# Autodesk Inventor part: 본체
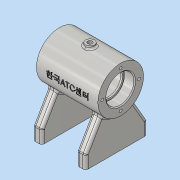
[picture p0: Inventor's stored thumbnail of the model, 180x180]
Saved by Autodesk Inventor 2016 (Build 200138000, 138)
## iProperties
Created: 2018-05
Part Number: 본체
Material: 알루미늄 6061
Document SubType Name: Modeling
Designer: Administrator
Density: 2.7 g/cm^3
Appearance: 알루미늄 - 평지
Mass: 317.681 g
Surface Area: 375.828 cm^2
Volume: 117.66 cm^3
Author: Administrator
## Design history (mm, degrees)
sketch "스케치1"
  geometry: L1 (-25, 0)-(0, 0); L2 (-20, 35)-(-30, 35); L3 (-30, 35)-(-30, -35); L4 (-30, -35)-(-20, -35); L5 (-20, -35)-(-20, 35); L6 (-20, 35)-(-30, -35); L7 (-30, 35)-(-20, -35)
  constraints: 14 end point, 2 horizontal, 2 midpoint, 2 parallel, 1 perpendicular
  dimensions: "d0" = 25 distance of L1.start L1.end; "d1" = 10 distance of L4.end L3.end; "d2" = 70 distance of L3.end L2.end
extrude "돌출1" new body sketch "스케치1" distance "d3" = 15; taper "d4" = 0 deg
sketch "스케치2"
  geometry: L1 (35, 65)-(-35, 65); L2 (35, 65)-(35, 91); L3 (35, 91)-(-35, 91); L4 (-35, 91)-(-35, 65); 2 further points
  constraints: 8 end point, 2 perpendicular, 1 horizontal, 1 midpoint, 1 vertical, 1 vertical alignment
  dimensions: "d5" = 65 distance from line of point (0, 0) L1; "d6" = 70 distance of L1.start L1.end; "d7" = 52 diameter of L3 L1
revolve "회전1" sketch "스케치2" stored, may be unused: angle "d8" = 90 deg
node "작업 평면1"
sketch "스케치3"
  geometry: L1 (-35, 15)-(35, 15) reference; L2 (-35, 15)-(-16.972, 46.226); L3 (-35, 0)-(-35, 15) reference; L4 (0, 0)-(0, 66.177); L5 (35, 15)-(16.972, 46.226); L6 (-35, 15)-(35, 15); L7 (-16.972, 46.226)-(16.972, 46.226)
  constraints: 10 end point, 1 collinear, 1 perpendicular, 1 symmetric about line, 1 vertical
  dimensions: "d10" = 30 deg angle of L3 L2
extrude "돌출2" join sketch "스케치3" stored distance "d11" = 10; taper "d12" = 0 deg
sketch "스케치4"
  geometry: L1 (35, 39)-(35, 91) reference; L2 (35, 65)-(-35, 65); L3 (-35, 39)-(-35, 91) reference; L4 (-35, 39)-(35, 39) reference; L5 (0, 39)-(0, 91); L6 (35, 65)-(35, 81); L7 (35, 81)-(23, 81); L8 (23, 81)-(23, 79); L9 (23, 79)-(21, 79); L10 (21, 79)-(21, 86); L11 (21, 86)-(0, 86); L12 (-23, 79)-(-21, 79); L13 (-35, 65)-(-35, 81); L14 (-35, 81)-(-23, 81); L15 (-23, 81)-(-23, 79); L16 (-21, 79)-(-21, 86); L17 (-21, 86)-(0, 86); 1 further point
  constraints: 28 end point, 5 symmetric about line, 4 perpendicular, 3 midpoint, 2 point on line, 1 horizontal, 1 vertical
  dimensions: "d13" = 32 diameter of L7 L2; "d14" = 28 diameter of L9 L2; "d15" = 42 diameter of L11 L2; "d16" = 12 distance of L6.end L7.end; "d17" = 21 distance of L10.end L11.end
revolve "회전2" sketch "스케치4" stored, may be unused: angle "d18" = 90 deg
node "작업 평면2"
sketch "스케치5"
  geometry: C1 r 5 at (0, 0); 1 further point
  constraints: 1 centre point, 1 coincident
  dimensions: "d20" = 10 diameter of C1
extrude "돌출3" join sketch "스케치5" stored distance "d21" = 10; taper "d22" = 0 deg
sketch "스케치7"
  geometry: 2 further points
  dimensions: "d34" = 20 vertical distance of point (30, -35) point (5, -55)
hole "구멍2" sketch "스케치7" at (5, -55) diameter "d35" = 4.134; stored, may be unused: countersink angle "d39" = 90 deg, drill point angle "d41" = 118 deg; dims "d36" = 8, "d37" = 4, "d38" = 2, "d40" = 10
sketch "스케치8"
  geometry: L1 (0, 65)-(8.893, 40.568); L2 (0, 65)-(0, 57.633); 2 further points
  constraints: 4 end point, 1 coincident, 1 vertical, 2 other
  dimensions: "d48" = 20 deg angle of L1 L2
node "작업 평면4"
  node "작업 평면3"
sketch "스케치9"
  geometry: C1 r 6 at (0, 0); 1 further point
  constraints: 1 centre point
  dimensions: "d50" = 12 diameter of C1
extrude "돌출4" join sketch "스케치9" stored distance "d51" = 10; taper "d52" = 0 deg
hole "구멍3" diameter "d55" = 5.188; stored, may be unused: countersink angle "d59" = 90 deg, drill point angle "d61" = 118 deg; dims "d53" = 10, "d54" = 10, "d56" = 12, "d57" = 4, "d58" = 2, "d60" = 16
hole "구멍4" diameter "d64" = 5.188; stored, may be unused: countersink angle "d68" = 90 deg, drill point angle "d70" = 118 deg; dims "d62" = 10, "d63" = 10, "d65" = 12, "d66" = 4, "d67" = 2, "d69" = 16
node "작업 평면5"
sketch "스케치10"
  geometry: 2 further points
  constraints: 1 other
feature "엠보싱1" sketch "스케치10" dims "d71" = 0.5, "d72" = 0
fillet "모깎기1" dims "d73" = 2, "d74" = 3
chamfer "모따기1" distance "d75" = 1; stored, may be unused: second distance "d76" = 2, angle "d77" = 45 deg
fillet "모깎기2" dims "d78" = 3, "d79" = 0.3
sketch "스케치11"
  geometry: 3 further points
  constraints: 1 other
  dimensions: "d80" = 21 distance of point (0, 0) point (-21, 0)
hole "구멍5" sketch "스케치11" at (-21, 0) diameter "d81" = 3.242; stored, may be unused: countersink angle "d85" = 90 deg, drill point angle "d87" = 118 deg; dims "d82" = 8, "d83" = 4, "d84" = 2, "d86" = 10
node "솔리드1"
mirror "대칭1"
mirror "대칭2"
pattern_linear "직사각형 패턴1" dims "d44" = 40
pattern_circular "원형 패턴2" dims angle "d89" = 360 deg
mirror "대칭4"
other parameters: "d9" = 25, "d19" = 94, "d49" = 3
